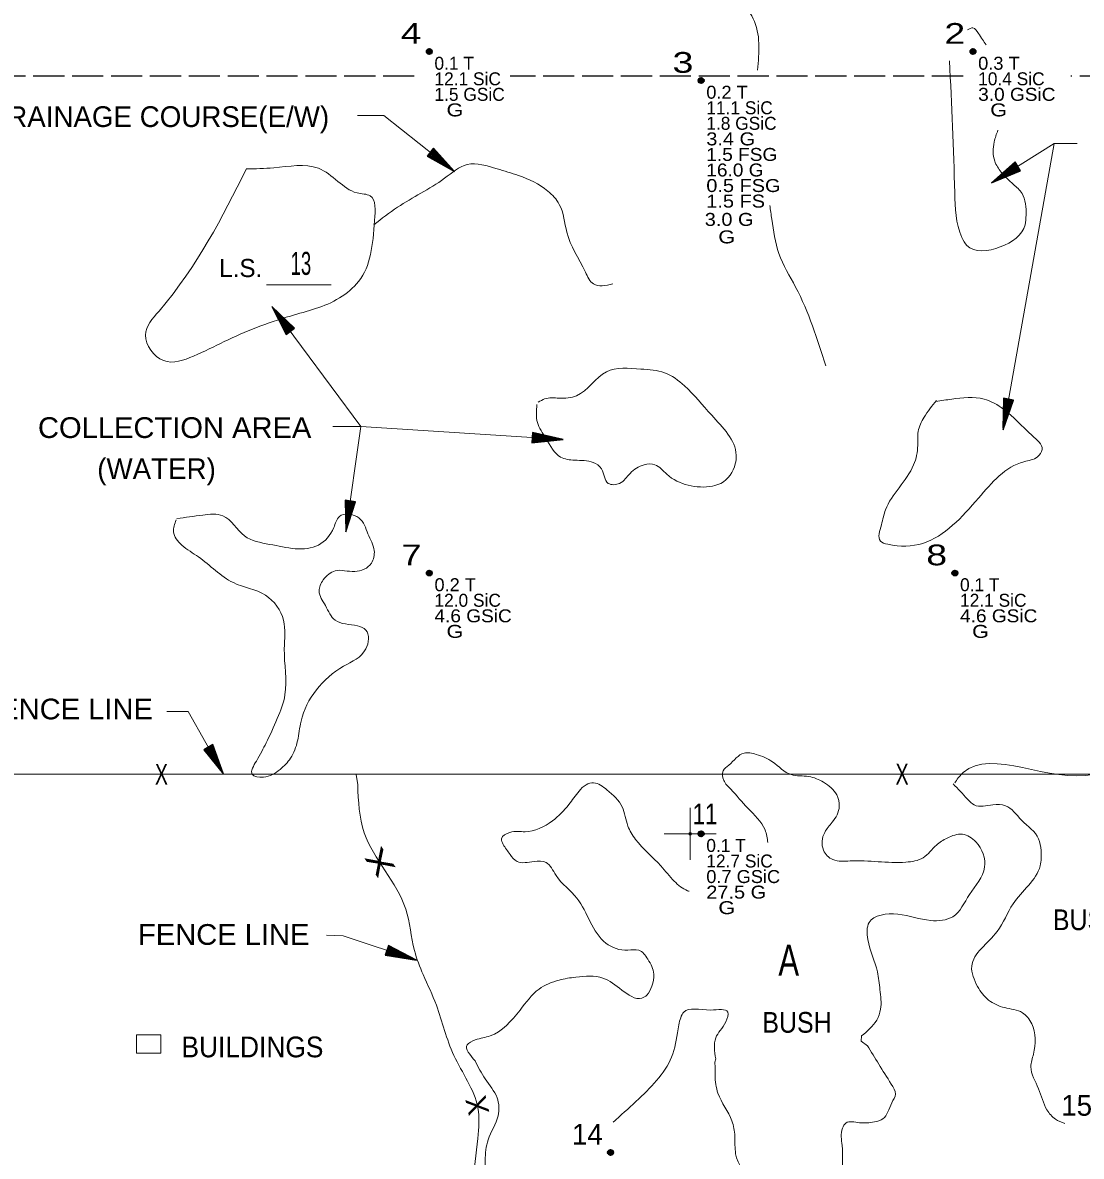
# Model space of a CAD drawing. Extents: x -496 to 480, y -450 to 700.
# Drawn here: x -257.6 to 150.9, y -124.4 to 312.9 of the extents above; entities that cross this region are included whole.
import ezdxf
from ezdxf.enums import TextEntityAlignment as Align

# ---------------------------------------------------------------- set-up
doc = ezdxf.new("R2010")
doc.units = 0
doc.header["$LTSCALE"] = 2
doc.header["$PDMODE"] = 32
doc.header["$PDSIZE"] = 1
doc.linetypes.add('LONG_DASHED', pattern=[7.5, 6, -1.5])
for name, color, linetype, lineweight in [('1', 7, 'Continuous', 13), ('2', 7, 'Continuous', 35), ('3', 7, 'Continuous', 13), ('4', 7, 'Continuous', 25)]:
    doc.layers.add(name, color=color, linetype=linetype, lineweight=lineweight)

msp = doc.modelspace()

# ---------------------------------------------------------------- linework, layer by layer
at = {"layer": '1'}
for p, q in [((-163.533, 211.85), (-138.533, 211.85)), ((-0.017, -10.027), (-0.017, 9.973)), ((-10.017, -0.027), (9.983, -0.027))]:
    msp.add_line(p, q, dxfattribs=at)
for p in [(0, 0), (0.001, -0.011)]:
    msp.add_point(p, dxfattribs=at)
at = {"layer": '2', "linetype": 'LONG_DASHED', "lineweight": 25}
for p, q in [((-106.483, 292.339), (-292.391, 292.339)), ((105.269, 292.339), (-69.524, 292.339)), ((402.281, 292.339), (146.811, 292.339))]:
    msp.add_line(p, q, dxfattribs=at)
at = {"layer": '2'}
for centre in [(-100.698, 301.781), (109.102, 301.781), (4.202, 290.604), (-100.698, 100.605), (102.108, 100.605), (4.202, 0.018), (-30.765, -122.923)]:
    msp.add_circle(centre, 1, dxfattribs=at)
for points in [[(-100.709, 302.668), (-99.978, 302.263), (-99.827, 301.415), (-100.512, 300.887), (-101.321, 301.117), (-101.607, 301.876), (-101.36, 302.437), (-100.787, 302.606), (-100.113, 302.112), (-100.13, 301.37), (-100.647, 301.112), (-101.169, 301.28), (-101.394, 301.926), (-100.81, 302.392), (-100.372, 301.859), (-100.411, 301.376), (-101.04, 301.511), (-100.894, 302.145), (-100.602, 301.595)], [(109.091, 302.668), (109.821, 302.263), (109.973, 301.415), (109.288, 300.887), (108.479, 301.117), (108.192, 301.876), (108.439, 302.437), (109.012, 302.606), (109.686, 302.112), (109.67, 301.37), (109.153, 301.112), (108.63, 301.28), (108.406, 301.926), (108.99, 302.392), (109.428, 301.859), (109.389, 301.376), (108.76, 301.511), (108.906, 302.145), (109.198, 301.595)], [(4.191, 291.491), (4.921, 291.087), (5.073, 290.239), (4.388, 289.711), (3.579, 289.941), (3.292, 290.699), (3.54, 291.261), (4.113, 291.429), (4.787, 290.935), (4.77, 290.194), (4.253, 289.935), (3.731, 290.104), (3.506, 290.75), (4.09, 291.216), (4.528, 290.682), (4.489, 290.199), (3.86, 290.334), (4.006, 290.969), (4.298, 290.418)], [(-100.709, 101.492), (-99.978, 101.088), (-99.827, 100.24), (-100.512, 99.712), (-101.321, 99.942), (-101.607, 100.7), (-101.36, 101.262), (-100.787, 101.43), (-100.113, 100.936), (-100.13, 100.195), (-100.647, 99.936), (-101.169, 100.105), (-101.394, 100.751), (-100.81, 101.217), (-100.372, 100.683), (-100.411, 100.2), (-101.04, 100.335), (-100.894, 100.97), (-100.602, 100.419)], [(102.098, 101.492), (102.828, 101.088), (102.98, 100.24), (102.294, 99.712), (101.486, 99.942), (101.199, 100.7), (101.446, 101.262), (102.019, 101.43), (102.693, 100.936), (102.676, 100.195), (102.16, 99.936), (101.637, 100.105), (101.413, 100.751), (101.997, 101.217), (102.435, 100.683), (102.395, 100.2), (101.766, 100.335), (101.912, 100.97), (102.205, 100.419)], [(4.191, 0.905), (4.921, 0.5), (5.073, -0.348), (4.388, -0.876), (3.579, -0.646), (3.292, 0.113), (3.54, 0.674), (4.113, 0.843), (4.787, 0.349), (4.77, -0.393), (4.253, -0.651), (3.731, -0.483), (3.506, 0.163), (4.09, 0.629), (4.528, 0.096), (4.489, -0.387), (3.86, -0.252), (4.006, 0.382), (4.298, -0.168)], [(-30.775, -122.036), (-30.045, -122.44), (-29.894, -123.289), (-30.579, -123.817), (-31.388, -123.586), (-31.674, -122.828), (-31.427, -122.266), (-30.854, -122.098), (-30.18, -122.592), (-30.197, -123.334), (-30.714, -123.592), (-31.236, -123.423), (-31.461, -122.777), (-30.877, -122.311), (-30.438, -122.845), (-30.478, -123.328), (-31.107, -123.193), (-30.961, -122.558), (-30.669, -123.109)]]:
    msp.add_spline(points, degree=3, dxfattribs=at)
at = {"layer": '3'}
for p, q in [((324.354, 23.005), (-397.391, 23.005)), ((-128.313, 18.951), (-128.943, 22.863))]:
    msp.add_line(p, q, dxfattribs=at)
msp.add_lwpolyline([(-213.648, -77.589), (-204.234, -77.589), (-204.234, -84.641), (-213.648, -84.641)], close=True, dxfattribs=at)
for points in [[(68.367, -81.729), (65.963, -80.016), (66.091, -77.963)], [(9.582, -90.11), (9.528, -88.131), (9.839, -86.822)]]:
    msp.add_lwpolyline(points, dxfattribs=at)
for points in [[(14.079, 391.089), (10.669, 381.892), (15.784, 367.246), (20.558, 354.303), (18.512, 335.229), (19.194, 323.308), (24.309, 314.452), (26.006, 294.553)], [(-360.928, 32.503), (-364.618, 32.503), (-370.152, 36.803), (-366.462, 52.771), (-367.077, 89.622), (-367.692, 111.733), (-367.692, 129.544), (-365.233, 204.474), (-367.692, 222.9), (-367.692, 241.939), (-367.692, 275.719), (-367.692, 294.145), (-370.152, 319.326), (-368.307, 346.964), (-367.077, 354.949), (-364.003, 361.705), (-358.469, 367.232), (-350.475, 372.146), (-328.339, 369.075), (-249.018, 367.232), (-212.739, 369.075), (-184.454, 370.303), (-156.784, 369.075), (-126.039, 369.689), (-110.052, 371.532), (-86.686, 369.689), (-25.196, 366.618), (-14.128, 369.075), (5.548, 370.303), (27.07, 370.918), (45.517, 368.461), (60.889, 369.075)], [(-360.928, 32.503), (-354.165, 42.33), (-351.09, 51.543), (-352.935, 81.024), (-355.394, 107.433), (-352.32, 127.087), (-351.09, 165.167), (-353.55, 187.891), (-353.55, 218.6), (-356.009, 235.798), (-352.32, 258.522), (-350.475, 281.861), (-352.32, 308.271), (-354.165, 323.011), (-355.394, 336.523), (-355.394, 346.964), (-351.705, 352.492), (-338.792, 357.406), (-308.048, 357.406), (-285.911, 359.862), (-274.228, 356.791), (-261.93, 352.492), (-249.018, 349.421), (-239.179, 350.65), (-224.422, 355.563), (-221.347, 356.177), (-209.664, 351.264), (-194.292, 346.964), (-171.541, 347.579), (-160.473, 350.65), (-154.939, 353.72), (-145.101, 357.406), (-140.796, 358.634), (-130.958, 358.634), (-102.673, 358.02), (-94.064, 356.791), (-86.686, 353.72), (-69.469, 350.035), (-56.556, 344.508), (-35.035, 344.508), (-21.507, 347.579), (-10.439, 346.964), (8.623, 345.736), (21.536, 349.421), (27.07, 352.492), (41.212, 356.177), (52.895, 357.406)], [(106.958, 310.163), (109.103, 310.942), (111.248, 308.8), (114.145, 304.366)], [(118.698, 271.416), (117.293, 266.924), (117.488, 259.522), (120.023, 255.237), (124.703, 250.563), (128.018, 247.057), (129.577, 238.682), (129.187, 234.981), (119.633, 226.411), (106.763, 226.995), (104.813, 230.112), (102.083, 247.252), (100.074, 298.197)], [(-171.31, 256.554), (-160.675, 256.941), (-143.465, 256.747), (-135.923, 251.726), (-128.575, 247.283), (-123.547, 246.124), (-121.807, 236.66), (-127.995, 213.096), (-135.343, 206.722), (-154.293, 199.769), (-179.818, 189.919), (-191.614, 184.317), (-203.216, 182.579), (-210.178, 192.43), (-204.956, 201.701), (-171.31, 256.361)], [(-122.086, 234.988), (-112.936, 241.751), (-94.82, 252.901), (-86.036, 258.202), (-74.507, 256.557), (-66.272, 253.998), (-54.926, 247.966), (-50.534, 242.848), (-47.606, 232.064), (-40.469, 216.71), (-37.358, 212.14), (-29.855, 212.14)], [(30.689, 242.429), (31.47, 237.135), (34.198, 223.851), (40.677, 210.908), (52.271, 180.594)], [(-58.622, 166.535), (-56.17, 167.76), (-50.565, 168.11), (-43.908, 168.984), (-32.347, 178.258), (-19.034, 179.308), (-9.925, 177.908), (-2.217, 172.834), (8.293, 161.461), (17.752, 146.063), (17.402, 142.739), (11.796, 135.215), (8.643, 134.166), (-0.816, 134.516), (-9.049, 138.715), (-13.603, 142.389), (-17.808, 142.389), (-23.238, 139.065), (-27.267, 135.215), (-31.646, 135.215), (-34.274, 140.814), (-37.427, 143.264), (-44.609, 144.139), (-50.039, 145.364), (-55.645, 152.537), (-58.973, 158.661), (-59.148, 165.66)], [(94.79, 166.824), (100.92, 167.698), (113.355, 167.698), (120.887, 163.85), (131.921, 153.703), (135.774, 148.279), (134.023, 145.48), (128.768, 143.556), (111.254, 129.56), (89.71, 112.066), (76.224, 111.716), (73.422, 112.941), (73.772, 119.239), (75.348, 125.012), (86.207, 142.331), (87.784, 149.854), (87.959, 155.277), (90.236, 160.701), (94.965, 167.174)], [(-198.084, 121.627), (-188.128, 122.971), (-180.325, 122.702), (-171.984, 114.908), (-162.297, 111.683), (-143.462, 111.414), (-137.542, 118.133), (-135.39, 122.433), (-127.856, 121.896), (-124.358, 115.714), (-121.936, 109.264), (-123.012, 104.426), (-129.47, 101.201), (-137.004, 101.47), (-141.578, 97.976), (-143.193, 93.676), (-140.771, 88.032), (-137.004, 82.388), (-128.394, 80.238), (-125.165, 78.625), (-125.165, 71.369), (-133.775, 64.649), (-150.189, 43.417), (-151.534, 35.892), (-154.225, 29.173), (-158.261, 24.873), (-164.719, 21.916), (-169.024, 22.991), (-167.409, 28.098), (-163.642, 35.086), (-159.337, 44.492), (-156.377, 53.63), (-156.646, 71.369), (-156.916, 82.388), (-163.911, 92.063), (-176.289, 96.901), (-189.743, 106.845), (-196.2, 111.414), (-199.429, 116.521), (-198.353, 121.09)], [(29.934, -3.399), (28.86, 1.552), (22.246, 9.87), (15.633, 17.21), (12.939, 20.635), (12.694, 24.305), (14.898, 26.507), (20.777, 31.155), (25.431, 30.666), (31.799, 27.73), (38.903, 22.837), (45.761, 22.103), (51.395, 19.901), (56.538, 15.008), (57.518, 10.604), (54.824, 4.488), (51.885, 0.573), (51.395, -6.277), (55.069, -9.947), (61.682, -10.437), (83.237, -10.926), (89.851, -9.213), (94.994, -4.32), (99.158, -1.629), (105.037, -0.161), (110.181, -3.097), (113.61, -12.883), (107.731, -23.404), (101.363, -31.967), (92.79, -33.435), (80.053, -30.988), (69.031, -34.169), (68.541, -40.774), (72.215, -53.252), (73.195, -60.102), (73.439, -67.687), (71.97, -71.846), (66.091, -77.963)], [(102.089, 19.626), (103.394, 21.581), (152.651, 22.558), (155.913, 22.558), (158.849, 15.716), (163.09, 3.009), (164.721, 1.054), (170.592, 0.728), (177.117, 4.638), (187.881, 11.806), (198.972, 17.671), (206.149, 21.581), (230.288, 21.255), (245.293, 21.581), (247.251, 20.603), (248.555, 13.761), (242.031, 3.66), (236.812, 0.402), (230.288, -3.182), (219.849, -12.305), (218.218, -18.17), (220.176, -32.181), (223.111, -38.697), (229.636, -49.124), (231.593, -54.011), (230.94, -60.853), (227.678, -68.347), (226.373, -74.538), (229.309, -83.335), (232.898, -90.178)], [(-128.313, 18.951), (-125.783, 0.424), (-109.764, -29.051), (-106.391, -45.052), (-103.019, -54.316), (-97.96, -66.106), (-91.215, -85.475), (-81.941, -105.686), (-81.941, -117.476), (-84.47, -135.161), (-90.372, -165.478), (-92.058, -189.058), (-98.803, -201.691), (-111.45, -230.324), (-133.371, -253.061), (-142.646, -263.167), (-157.822, -273.273), (-183.115, -284.221), (-215.154, -299.379), (-232.859, -301.064), (-256.467, -300.221), (-272.486, -305.274), (-287.662, -311.169), (-297.78, -312.854), (-318.014, -311.169), (-339.936, -301.906), (-352.582, -299.379), (-370.288, -290.958), (-384.621, -289.274), (-392.209, -288.431), (-393.895, -284.221)], [(-72.208, -4.101), (-72.791, -1.874), (-69.607, 0.573), (-63.729, 0.818), (-53.196, 4.977), (-46.827, 11.338), (-42.908, 16.476), (-40.214, 18.922), (-37.275, 19.656), (-32.131, 16.965), (-26.252, 10.359), (-24.048, 3.02), (-21.108, -2.118), (-11.311, -12.394), (-6.167, -18.266), (-1.023, -21.936), (-0.372, -22.157)], [(144.547, -111.697), (140.908, -110.053), (137.646, -106.469), (134.384, -98.323), (131.448, -89.852), (132.426, -84.965), (131.774, -73.235), (128.186, -68.999), (121.335, -67.044), (115.138, -64.112), (110.897, -58.898), (108.613, -51.079), (118.4, -37.72), (124.598, -26.967), (135.036, -12.305), (135.362, -6.44), (134.384, -1.879), (127.86, 5.29), (121.662, 10.829), (116.769, 11.154), (109.592, 11.154), (106.982, 13.435), (101.437, 19.3)], [(-82.993, -87.592), (-86.075, -81.436), (-82.993, -79.512), (-77.216, -77.973), (-65.66, -67.969), (-58.341, -59.89), (-50.637, -56.427), (-44.089, -55.273), (-33.688, -55.657), (-26.369, -60.274), (-18.666, -63.352), (-16.74, -62.198), (-14.814, -58.735), (-14.043, -54.118), (-16.354, -48.347), (-19.821, -44.884), (-24.058, -44.884), (-32.533, -42.191), (-43.703, -24.877), (-51.792, -16.028), (-55.644, -11.026), (-60.267, -10.641), (-66.815, -10.641), (-69.512, -7.948), (-72.208, -4.101)], [(9.839, -86.822), (9.839, -78.742), (13.691, -72.586), (14.461, -68.739), (7.913, -67.969), (-2.487, -68.739), (-4.413, -73.741), (-6.724, -84.899), (-19.821, -102.212), (-28.681, -110.292), (-29.759, -111.275)], [(68.367, -81.729), (77.589, -96.508), (79.212, -100.399), (77.751, -103.804), (74.342, -109.966), (71.095, -111.101), (65.252, -111.425), (60.057, -111.587), (58.758, -113.533), (58.596, -120.181), (58.758, -142.881), (58.758, -144.502), (54.538, -145.151), (40.415, -144.989), (34.896, -142.719), (24.506, -134.774), (17.526, -123.424), (17.201, -116.614), (16.065, -110.776), (10.708, -100.075), (9.572, -93.103), (9.582, -90.11)], [(-8.793, -151.534), (-6.724, -153.384), (-0.561, -161.464), (6.758, -174.93), (11.38, -184.549), (9.069, -193.783), (4.061, -199.554), (-3.258, -205.71), (-10.576, -210.712), (-16.74, -211.482), (-23.673, -212.636), (-27.91, -218.792), (-30.607, -223.794), (-30.992, -231.874), (-26.755, -237.26), (-22.132, -242.647), (-11.347, -246.109), (-0.946, -246.879), (5.602, -245.725), (5.987, -241.492), (4.061, -234.182), (-0.946, -224.179), (-2.102, -215.714), (0.209, -210.712), (9.839, -202.248), (17.158, -200.324), (21.395, -200.709), (23.706, -204.556), (22.551, -218.407), (23.706, -240.723), (24.862, -247.648), (27.943, -253.035), (28.714, -256.498), (25.632, -262.269), (18.699, -266.116), (12.535, -268.81), (5.217, -268.425), (-4.413, -263.038), (-11.347, -257.267), (-33.688, -256.498), (-39.081, -255.728), (-41.392, -252.65), (-43.703, -248.803), (-52.178, -246.109), (-60.652, -246.879), (-66.045, -248.803), (-67.2, -254.574), (-73.749, -265.347), (-76.83, -266.886), (-88.001, -266.501), (-94.935, -263.038), (-103.409, -254.574), (-105.72, -246.109), (-102.253, -234.182), (-99.942, -219.562), (-95.705, -213.405), (-87.616, -211.866), (-79.527, -211.482), (-74.519, -209.173), (-64.889, -187.627), (-59.882, -178.393), (-54.874, -173.776), (-50.637, -173.391), (-46.015, -173.776), (-38.311, -171.468), (-34.459, -168.39), (-33.688, -163.003), (-33.688, -158.771), (-42.548, -157.617), (-59.496, -157.232), (-68.741, -151.461), (-78.371, -136.84), (-79.142, -126.067), (-77.986, -117.987), (-74.134, -108.753), (-74.519, -101.828), (-79.142, -94.517), (-82.993, -87.592)]]:
    msp.add_spline(points, degree=3, dxfattribs=at)
at = {"layer": '4', "lineweight": 13}
for p, q in [((140.404, 266.337), (120.704, 155.89)), ((-127.136, 157.159), (-132.855, 116.535)), ((-127.136, 157.159), (-48.971, 152.081))]:
    msp.add_line(p, q, dxfattribs=at)
for points in [[(-128.407, 277.127), (-118.239, 277.127), (-90.913, 255.546)], [(149.301, 266.337), (140.404, 266.337), (116.255, 251.103)], [(-137.939, 157.159), (-127.136, 157.159), (-161.452, 203.496)], [(-201.925, 47.186), (-193.687, 47.186), (-180.118, 22.985)], [(-140.315, -39.086), (-133.904, -39.377), (-105.633, -48.692)]]:
    msp.add_lwpolyline(points, dxfattribs=at)
at = {"layer": '4'}
for points in [[(-90.913, 255.546), (-99.091, 264.553), (-101.57, 261.414)], [(116.255, 251.103), (127.472, 255.814), (125.338, 259.197)], [(-161.452, 203.496), (-155.918, 192.663), (-152.703, 195.043)], [(120.704, 155.89), (124.78, 167.352), (120.842, 168.055)], [(-48.971, 152.081), (-60.816, 154.855), (-61.076, 150.864)], [(-132.855, 116.535), (-129.202, 128.139), (-133.163, 128.697)], [(-180.118, 22.985), (-184.242, 34.43), (-187.731, 32.474)], [(-105.633, -48.692), (-116.404, -43.037), (-117.656, -46.836)]]:
    msp.add_lwpolyline(points, close=True, dxfattribs=at)
for points in [[(-99.087, 264.399), (-91.363, 255.902), (-101.341, 261.442), (-99.161, 264.236), (-91.941, 256.359), (-101.082, 261.456), (-99.119, 264.011), (-92.552, 256.841), (-100.794, 261.506), (-99.151, 263.762), (-93.233, 257.406), (-100.486, 261.511), (-99.115, 263.456), (-94.051, 258.081), (-100.173, 261.594), (-99.107, 263.119), (-94.936, 258.807), (-99.752, 261.675), (-99.05, 262.773), (-95.881, 259.636), (-99.32, 261.664), (-98.956, 262.368), (-97.065, 260.544), (-98.788, 261.71)], [(127.326, 255.861), (116.741, 251.408), (125.287, 258.971), (127.196, 255.985), (117.364, 251.801), (125.214, 258.722), (126.971, 256.021), (118.022, 252.216), (125.166, 258.434), (126.746, 256.134), (118.782, 252.671), (125.068, 258.142), (126.446, 256.202), (119.691, 253.217), (125.042, 257.819), (126.125, 256.306), (120.67, 253.81), (124.978, 257.395), (125.78, 256.368), (121.767, 254.425), (124.825, 256.992), (125.367, 256.414), (123.017, 255.238), (124.691, 256.475)], [(-155.881, 192.812), (-161.112, 203.035), (-152.932, 195.076), (-155.768, 192.951), (-160.673, 202.443), (-153.186, 195.131), (-155.749, 193.178), (-160.21, 201.817), (-153.477, 195.157), (-155.653, 193.41), (-159.7, 201.094), (-153.775, 195.233), (-155.607, 193.715), (-159.088, 200.227), (-154.099, 195.235), (-155.527, 194.042), (-158.423, 199.296), (-154.526, 195.267), (-155.492, 194.391), (-157.728, 198.248), (-154.94, 195.39), (-155.476, 194.806), (-156.824, 197.062), (-155.466, 195.485)], [(124.646, 167.277), (120.805, 156.455), (120.975, 167.866), (124.467, 167.264), (120.935, 157.18), (121.109, 167.644), (124.289, 167.122), (121.071, 157.946), (121.29, 167.414), (124.054, 167.032), (121.247, 158.813), (121.44, 167.145), (123.802, 166.856), (121.456, 159.854), (121.661, 166.908), (123.508, 166.689), (121.678, 160.976), (121.931, 166.575), (123.23, 166.475), (121.962, 162.201), (122.126, 166.19), (122.918, 166.202), (122.204, 163.673), (122.417, 165.743)], [(-60.726, 154.731), (-49.544, 152.119), (-60.903, 151.017), (-60.694, 154.554), (-50.279, 152.167), (-60.697, 151.175), (-60.532, 154.393), (-51.055, 152.218), (-60.489, 151.38), (-60.417, 154.17), (-51.937, 152.296), (-60.238, 151.559), (-60.214, 153.938), (-52.994, 152.388), (-60.027, 151.805), (-60.016, 153.666), (-54.134, 152.483), (-59.727, 152.11), (-59.772, 153.413), (-55.383, 152.629), (-59.366, 152.347), (-59.465, 153.133), (-56.873, 152.705), (-58.954, 152.687)], [(-129.333, 128.059), (-132.775, 117.103), (-133.023, 128.513), (-129.511, 128.04), (-132.672, 117.833), (-132.881, 128.296), (-129.684, 127.891), (-132.563, 118.603), (-132.692, 128.073), (-129.915, 127.792), (-132.42, 119.477), (-132.532, 127.81), (-130.161, 127.607), (-132.248, 120.524), (-132.303, 127.581), (-130.448, 127.43), (-132.068, 121.654), (-132.021, 127.259), (-130.718, 127.206), (-131.829, 122.888), (-131.812, 126.881), (-131.02, 126.921), (-131.642, 124.368), (-131.504, 126.444)], [(-184.298, 34.287), (-180.398, 23.486), (-187.508, 32.412), (-184.428, 34.163), (-180.759, 24.128), (-187.264, 32.326), (-184.475, 33.94), (-181.139, 24.807), (-186.979, 32.263), (-184.6, 33.722), (-181.554, 25.589), (-186.692, 32.15), (-184.683, 33.425), (-182.052, 26.526), (-186.371, 32.107), (-184.804, 33.111), (-182.593, 27.534), (-185.951, 32.022), (-184.883, 32.769), (-183.151, 28.661), (-185.556, 31.847), (-184.951, 32.359), (-183.898, 29.952), (-185.047, 31.687)], [(-116.348, -43.18), (-106.178, -48.512), (-117.45, -46.731), (-116.361, -43.359), (-106.878, -48.281), (-117.212, -46.63), (-116.246, -43.556), (-107.617, -48.038), (-116.959, -46.483), (-116.19, -43.801), (-108.45, -47.741), (-116.671, -46.373), (-116.051, -44.076), (-109.451, -47.387), (-116.405, -46.188), (-115.928, -44.39), (-110.531, -47.009), (-116.038, -45.967), (-115.755, -44.695), (-111.703, -46.555), (-115.629, -45.829), (-115.528, -45.043), (-113.126, -46.108), (-115.145, -45.603)]]:
    msp.add_lwpolyline(points, dxfattribs=at)

# ---------------------------------------------------------------- texts
at = {"layer": '1', "width": 0.6}
msp.add_text('13', height=8.89, dxfattribs=at).set_placement((-150.235, 215.639), align=Align.CENTER)
at = {"layer": '1'}
msp.add_text('L.S.', height=7, dxfattribs=at).set_placement((-173.44, 214.794), align=Align.CENTER)
at = {"layer": '2'}
for s, width, p in [('  4', 1.35, (-103.698, 304.781)), ('  2', 1.35, (106.101, 304.781)), ('  3', 1.35, (1.202, 293.604)), ('  7', 1.3, (-103.698, 103.605)), ('  8', 1.35, (99.108, 103.605)), (' 11', 0.8, (10.445, 3.654))]:
    msp.add_text(s, height=8, dxfattribs=dict(at, width=width)).set_placement(p, align=Align.RIGHT)
for s, p in [('0.1 T      ', (-98.698, 294.781)), ('12.1 SiC   ', (-98.698, 288.781)), ('10.4 SiC   ', (111.102, 288.781)), ('1.5 GSiC   ', (-98.698, 282.781)), ('11.1 SiC   ', (6.202, 277.604)), ('1.8 GSiC   ', (6.202, 271.604)), ('0.1 T      ', (104.108, 93.605)), ('12.0 SiC   ', (-98.698, 87.605)), ('12.1 SiC   ', (104.108, 87.605)), ('0.1 T      ', (6.202, -6.982)), ('12.7 SiC   ', (6.202, -12.982))]:
    msp.add_text(s, height=5, dxfattribs=at).set_placement(p)
for s, width, p in [('0.3 T      ', 1.05, (111.102, 294.781)), ('0.2 T      ', 1.05, (6.202, 283.604)), ('3.0 GSiC   ', 1.1, (111.102, 282.781)), ('  G        ', 1.25, (-98.698, 276.781)), ('  G        ', 1.25, (111.102, 276.781)), ('3.4 G      ', 1.15, (6.202, 265.604)), ('1.5 FSG    ', 1.1, (6.202, 259.604)), ('16.0 G     ', 1.1, (6.202, 253.604)), ('0.5 FSG    ', 1.15, (6.202, 247.604)), ('1.5 FS     ', 1.15, (6.202, 241.604)), ('3.0 G      ', 1.15, (5.603, 234.541)), ('  G        ', 1.25, (6.177, 227.798)), ('0.2 T      ', 1.05, (-98.698, 93.605)), ('4.6 GSiC   ', 1.1, (-98.698, 81.605)), ('4.6 GSiC   ', 1.1, (104.108, 81.605)), ('  G        ', 1.25, (-98.698, 75.605)), ('  G        ', 1.25, (104.108, 75.605)), ('0.7 GSiC   ', 1.05, (6.202, -18.982)), ('27.5 G     ', 1.15, (6.202, -24.982)), ('  G        ', 1.25, (6.202, -30.982))]:
    msp.add_text(s, height=5, dxfattribs=dict(at, width=width)).set_placement(p)
at = {"layer": '2', "width": 0.75}
msp.add_text('A', height=12, dxfattribs=at).set_placement((38.006, -54.773), align=Align.CENTER)
at = {"layer": '2'}
for s, p in [(' 15', (155.055, -108.747)), (' 14', (-33.765, -119.923))]:
    msp.add_text(s, height=8, dxfattribs=at).set_placement(p, align=Align.RIGHT)
at = {"layer": '3', "width": 0.7}
for p in [(-204.039, 18.977), (81.738, 19.021)]:
    msp.add_text('X', height=8, dxfattribs=at).set_placement(p, align=Align.CENTER)
at = {"layer": '3', "width": 1.5}
msp.add_text('X', height=8, rotation=124.511, dxfattribs=at).set_placement((-116.482, -8.768), align=Align.CENTER)
at = {"layer": '3'}
msp.add_text('X', height=8, rotation=102.543, dxfattribs=at).set_placement((-78.275, -104.019), align=Align.CENTER)
at = {"layer": '4'}
for s, p in [('DRAINAGE COURSE(E/W)', (-205.301, 272.684)), ('(WATER)', (-205.936, 136.847))]:
    msp.add_text(s, height=8, dxfattribs=at).set_placement(p, align=Align.CENTER)
for s, width, p in [('COLLECTION AREA', 1.05, (-198.946, 152.716)), ('FENCE LINE', 1.05, (-240.416, 44.159)), ('BUSH', 0.9, (153.299, -37.149)), ('FENCE LINE', 1.05, (-180.008, -42.821)), ('BUSH', 0.9, (41.191, -76.727)), ('BUILDINGS', 0.95, (-168.931, -86.208))]:
    msp.add_text(s, height=8, dxfattribs=dict(at, width=width)).set_placement(p, align=Align.CENTER)

doc.saveas('drawing.dxf')
